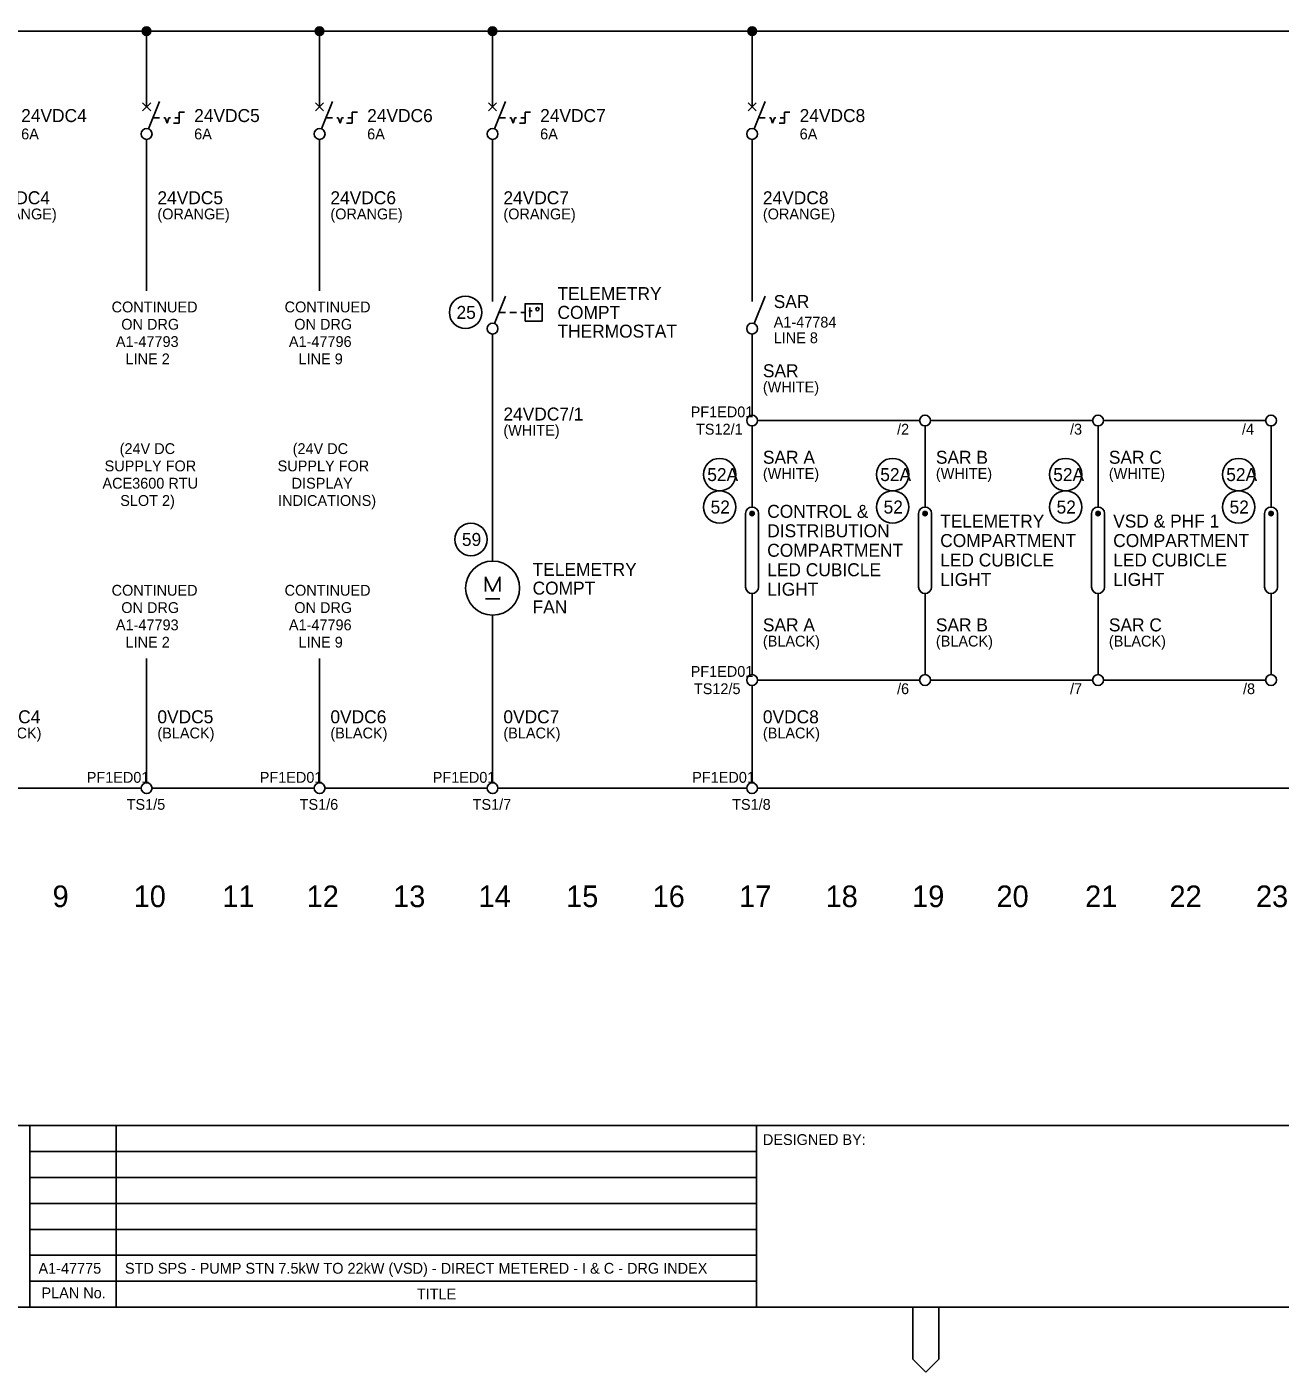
# Model space of a CAD drawing. Extents: x 0 to 841, y 0 to 594.
# Drawn here: x 212.3 to 502.1, y 0 to 311 of the extents above; entities that cross this region are included whole.
import ezdxf

# ---------------------------------------------------------------- set-up
doc = ezdxf.new("R2010")
doc.units = 0
for name, color, linetype in [('A1BORDER', 7, 'Continuous'), ('Level 1', 7, 'Continuous'), ('Level 10', 7, 'Continuous')]:
    doc.layers.add(name, color=color, linetype=linetype)

msp = doc.modelspace()

# ---------------------------------------------------------------- linework, layer by layer
at = {"layer": 'A1BORDER'}
for p, q in [((28, 57), (829, 57)), ((213, 15), (213, 57)), ((233, 15), (233, 57)), ((381, 15), (381, 57)), ((213, 51), (381, 51)), ((213, 45), (381, 45)), ((213, 39), (381, 39)), ((213, 33), (381, 33)), ((213, 27), (381, 27)), ((213, 21), (381, 21)), ((829, 15), (28, 15)), ((417.19, 15), (417.19, 3)), ((423.19, 15), (423.19, 3)), ((417.19, 3), (420.19, 0)), ((423.19, 3), (420.19, 0))]:
    msp.add_line(p, q, dxfattribs=at)
at = {"layer": 'Level 1'}
for p, q in [((80, 310), (580, 310)), ((240, 310), (240, 295)), ((280, 310), (280, 295)), ((320, 310), (320, 295)), ((380, 310), (380, 295)), ((239.06, 293.44), (240.94, 291.56)), ((240.94, 293.44), (239.06, 291.56)), ((240, 292.5), (240, 295)), ((240.46, 287.41), (243, 293.75)), ((279.06, 293.44), (280.94, 291.56)), ((280.94, 293.44), (279.06, 291.56)), ((280, 292.5), (280, 295)), ((280.46, 287.41), (283, 293.75)), ((319.06, 293.44), (320.94, 291.56)), ((320.94, 293.44), (319.06, 291.56)), ((320, 292.5), (320, 295)), ((320.46, 287.41), (323, 293.75)), ((379.06, 293.44), (380.94, 291.56)), ((380.94, 293.44), (379.06, 291.56)), ((380, 292.5), (380, 295)), ((380.46, 287.41), (383, 293.75)), ((240, 285), (240, 250)), ((280, 285), (280, 250)), ((320, 285), (320, 250)), ((380, 285), (380, 250)), ((320, 247.5), (320, 250)), ((380, 247.5), (380, 250)), ((380, 250), (380, 250)), ((320.46, 242.41), (323, 248.75)), ((321.5, 245), (323, 245)), ((324, 245), (325.5, 245)), ((326.5, 245), (327.5, 245)), ((320, 240), (320, 187.5)), ((380, 240), (380, 240)), ((380, 221.25), (380, 240)), ((380, 200), (380, 218.75)), ((381.25, 220), (418.75, 220)), ((420, 200), (420, 218.75)), ((421.25, 220), (458.75, 220)), ((460, 200), (460, 218.75)), ((461.25, 220), (498.75, 220)), ((500, 200), (500, 218.75)), ((380, 161.25), (380, 180)), ((420, 161.25), (420, 180)), ((460, 161.25), (460, 180)), ((500, 161.25), (500, 180)), ((320, 136.25), (320, 175)), ((240, 136.25), (240, 165)), ((280, 136.25), (280, 165)), ((380, 136.25), (380, 158.75)), ((381.25, 160), (418.75, 160)), ((421.25, 160), (458.75, 160)), ((461.25, 160), (498.75, 160)), ((201.25, 135), (238.75, 135)), ((241.25, 135), (278.75, 135)), ((281.25, 135), (318.75, 135)), ((321.25, 135), (378.75, 135)), ((381.25, 135), (538.75, 135))]:
    msp.add_line(p, q, dxfattribs=at)
msp.add_lwpolyline([(327.5, 243), (331.5, 243), (331.5, 247), (327.5, 247)], close=True, dxfattribs=at)
for points in [[(328.63, 246.13), (328.63, 243.87)], [(330.36, 245.38), (330.18, 245.42), (330.05, 245.56), (329.99, 245.76), (330.05, 245.94), (330.18, 246.07), (330.36, 246.13), (330.56, 246.07), (330.7, 245.94), (330.74, 245.76), (330.7, 245.56), (330.56, 245.42), (330.36, 245.38)], [(328.38, 245.38), (329.13, 245.38)]]:
    msp.add_lwpolyline(points, dxfattribs=at)
for centre, radius in [((240, 286.25), 1.25), ((280, 286.25), 1.25), ((320, 286.25), 1.25), ((380, 286.25), 1.25), ((313.75, 245), 3.75), ((320, 241.25), 1.25), ((380, 220), 1.25), ((420, 220), 1.25), ((460, 220), 1.25), ((500, 220), 1.25), ((372.5, 207.5), 3.75), ((412.5, 207.5), 3.75), ((452.5, 207.5), 3.75), ((492.5, 207.5), 3.75), ((372.5, 200), 3.75), ((412.5, 200), 3.75), ((452.5, 200), 3.75), ((492.5, 200), 3.75), ((315, 192.5), 3.75), ((380, 160), 1.25), ((420, 160), 1.25), ((460, 160), 1.25), ((500, 160), 1.25)]:
    msp.add_circle(centre, radius, dxfattribs=at)
at = {"layer": 'Level 10'}
for p, q in [((239, 310), (240.99, 310)), ((239.05, 310.3), (240.95, 310.3)), ((239.05, 309.7), (240.95, 309.7)), ((239.2, 310.6), (240.8, 310.6)), ((239.2, 309.4), (240.8, 309.4)), ((239.56, 310.9), (240.44, 310.9)), ((239.56, 309.1), (240.44, 309.1)), ((240, 311), (240, 311)), ((279, 310), (280.99, 310)), ((279.05, 310.3), (280.95, 310.3)), ((279.05, 309.7), (280.95, 309.7)), ((279.2, 310.6), (280.8, 310.6)), ((279.2, 309.4), (280.8, 309.4)), ((279.56, 310.9), (280.44, 310.9)), ((279.56, 309.1), (280.44, 309.1)), ((280, 311), (280, 311)), ((319, 310), (320.99, 310)), ((319.05, 310.3), (320.95, 310.3)), ((319.05, 309.7), (320.95, 309.7)), ((319.2, 310.6), (320.8, 310.6)), ((319.2, 309.4), (320.8, 309.4)), ((319.56, 310.9), (320.44, 310.9)), ((319.56, 309.1), (320.44, 309.1)), ((320, 311), (320, 311)), ((379, 310), (380.99, 310)), ((379.05, 310.3), (380.95, 310.3)), ((379.05, 309.7), (380.95, 309.7)), ((379.2, 310.6), (380.8, 310.6)), ((379.2, 309.4), (380.8, 309.4)), ((379.56, 310.9), (380.44, 310.9)), ((379.56, 309.1), (380.44, 309.1)), ((380, 311), (380, 311)), ((241.5, 290), (243, 290)), ((244, 290), (244.33, 290)), ((244.75, 288.75), (244.33, 290)), ((244.75, 288.75), (245.17, 290)), ((245.5, 290), (245.17, 290)), ((246.5, 290), (247.5, 290)), ((247.5, 288.75), (247.5, 291.25)), ((247.5, 291.25), (248.75, 291.25)), ((281.5, 290), (283, 290)), ((284, 290), (284.33, 290)), ((284.75, 288.75), (284.33, 290)), ((284.75, 288.75), (285.17, 290)), ((285.5, 290), (285.17, 290)), ((286.5, 290), (287.5, 290)), ((287.5, 288.75), (287.5, 291.25)), ((287.5, 291.25), (288.75, 291.25)), ((321.5, 290), (323, 290)), ((324, 290), (324.33, 290)), ((324.75, 288.75), (324.33, 290)), ((324.75, 288.75), (325.17, 290)), ((325.5, 290), (325.17, 290)), ((326.5, 290), (327.5, 290)), ((327.5, 288.75), (327.5, 291.25)), ((327.5, 291.25), (328.75, 291.25)), ((381.5, 290), (383, 290)), ((384, 290), (384.33, 290)), ((384.75, 288.75), (384.33, 290)), ((384.75, 288.75), (385.17, 290)), ((385.5, 290), (385.17, 290)), ((386.5, 290), (387.5, 290)), ((387.5, 288.75), (387.5, 291.25)), ((387.5, 291.25), (388.75, 291.25)), ((246.25, 288.75), (247.5, 288.75)), ((286.25, 288.75), (287.5, 288.75)), ((326.25, 288.75), (327.5, 288.75)), ((386.25, 288.75), (387.5, 288.75)), ((380.46, 242.41), (383, 248.75)), ((378.5, 181.5), (378.5, 198.5)), ((379.5, 198.5), (379.5, 198.5)), ((379.8, 198.04), (379.8, 198.96)), ((380.1, 198.01), (380.1, 198.99)), ((380.4, 198.2), (380.4, 198.8)), ((381.5, 198.5), (381.5, 181.5)), ((418.5, 181.5), (418.5, 198.5)), ((419.5, 198.5), (419.5, 198.5)), ((419.8, 198.04), (419.8, 198.96)), ((420.1, 198.01), (420.1, 198.99)), ((420.4, 198.2), (420.4, 198.8)), ((421.5, 198.5), (421.5, 181.5)), ((458.5, 181.5), (458.5, 198.5)), ((459.5, 198.5), (459.5, 198.5)), ((459.8, 198.04), (459.8, 198.96)), ((460.1, 198.01), (460.1, 198.99)), ((460.4, 198.2), (460.4, 198.8)), ((461.5, 198.5), (461.5, 181.5)), ((498.5, 181.5), (498.5, 198.5)), ((499.5, 198.5), (499.5, 198.5)), ((499.8, 198.04), (499.8, 198.96)), ((500.1, 198.01), (500.1, 198.99)), ((500.4, 198.2), (500.4, 198.8)), ((501.5, 198.5), (501.5, 181.5)), ((318.33, 180.5), (318.33, 183.83)), ((318.33, 183.83), (320, 180.5)), ((320, 180.5), (321.67, 183.83)), ((321.67, 183.83), (321.67, 180.5)), ((318.34, 178.75), (321.68, 178.75))]:
    msp.add_line(p, q, dxfattribs=at)
for centre, radius in [((240, 310), 1), ((280, 310), 1), ((320, 310), 1), ((380, 310), 1), ((380, 241.25), 1.25), ((380, 198.5), 0.5), ((420, 198.5), 0.5), ((460, 198.5), 0.5), ((500, 198.5), 0.5), ((320, 181.25), 6.25), ((240, 135), 1.25), ((280, 135), 1.25), ((320, 135), 1.25), ((380, 135), 1.25)]:
    msp.add_circle(centre, radius, dxfattribs=at)
for centre, start, end in [((380, 198.5), 0, 180), ((420, 198.5), 0, 180), ((460, 198.5), 0, 180), ((500, 198.5), 0, 180), ((380, 181.5), 180, 0), ((420, 181.5), 180, 0), ((460, 181.5), 180, 0), ((500, 181.5), 180, 0)]:
    msp.add_arc(centre, 1.5, start, end, dxfattribs=at)

# ---------------------------------------------------------------- texts
at = {"layer": 'A1BORDER'}
for s, p in [('DESIGNED BY:', (382.5, 52.5)), ('PLAN No.', (215.69, 17.06)), ('TITLE', (302.5, 16.81))]:
    msp.add_text(s, height=2.5, dxfattribs=at).set_placement(p)
at = {"layer": 'Level 1'}
for s, height, p in [('24VDC4', 3, (211, 289)), ('24VDC5', 3, (251, 289)), ('24VDC6', 3, (291, 289)), ('24VDC7', 3, (331, 289)), ('24VDC8', 3, (391, 289)), ('6A', 2.5, (211, 285)), ('6A', 2.5, (251, 285)), ('6A', 2.5, (291, 285)), ('6A', 2.5, (331, 285)), ('6A', 2.5, (391, 285)), ('24VDC4', 3, (202.5, 270)), ('24VDC5', 3, (242.5, 270)), ('24VDC6', 3, (282.5, 270)), ('24VDC7', 3, (322.5, 270)), ('24VDC8', 3, (382.5, 270)), ('(ORANGE)', 2.5, (202.5, 266.5)), ('(ORANGE)', 2.5, (242.5, 266.5)), ('(ORANGE)', 2.5, (282.5, 266.5)), ('(ORANGE)', 2.5, (322.5, 266.5)), ('(ORANGE)', 2.5, (382.5, 266.5)), ('TELEMETRY', 3, (335, 247.84)), ('SAR', 3, (385, 246)), ('CONTINUED', 2.5, (231.91, 245)), ('CONTINUED', 2.5, (271.91, 245)), ('25', 3, (311.66, 243.5)), ('COMPT', 3, (335, 243.5)), ('ON DRG', 2.5, (234.15, 241)), ('ON DRG', 2.5, (274.15, 241)), ('A1-47784', 2.5, (385, 241.5)), ('A1-47793', 2.5, (232.9, 237)), ('A1-47796', 2.5, (272.9, 237)), ('THERMOSTAT', 3, (335, 239.16)), ('LINE 8', 2.5, (385, 237.88)), ('LINE 2', 2.5, (235.14, 233)), ('LINE 9', 2.5, (275.14, 233)), ('SAR', 3, (382.5, 230)), ('(WHITE)', 2.5, (382.5, 226.5)), ('24VDC7/1', 3, (322.5, 220)), ('PF1ED01', 2.5, (365.8, 220.74)), ('(WHITE)', 2.5, (322.5, 216.5)), ('TS12/1', 2.5, (367.04, 216.74)), ('/2', 2.5, (413.52, 216.74)), ('/3', 2.5, (453.52, 216.74)), ('/4', 2.5, (493.27, 216.74)), ('(24V DC', 2.5, (233.77, 212.25)), ('(24V DC', 2.5, (273.77, 212.25)), ('SAR A', 3, (382.5, 210)), ('SAR B', 3, (422.5, 210)), ('SAR C', 3, (462.5, 210)), ('SUPPLY FOR', 2.5, (230.29, 208.25)), ('SUPPLY FOR', 2.5, (270.29, 208.25)), ('52A', 3, (369.64, 206)), ('(WHITE)', 2.5, (382.5, 206.5)), ('52A', 3, (409.64, 206)), ('(WHITE)', 2.5, (422.5, 206.5)), ('52A', 3, (449.64, 206)), ('(WHITE)', 2.5, (462.5, 206.5)), ('52A', 3, (489.64, 206)), ('ACE3600 RTU', 2.5, (229.79, 204.25)), ('DISPLAY', 2.5, (273.53, 204.25)), ('SLOT 2)', 2.5, (233.9, 200.25)), ('INDICATIONS)', 2.5, (270.41, 200.25)), ('52', 3, (370.41, 198.5)), ('CONTROL &', 3, (383.5, 197.5)), ('52', 3, (410.41, 198.5)), ('52', 3, (450.41, 198.5)), ('52', 3, (490.41, 198.5)), ('DISTRIBUTION', 3, (383.5, 193)), ('TELEMETRY', 3, (423.5, 195.25)), ('VSD & PHF 1', 3, (463.5, 195.25)), ('59', 3, (312.91, 191)), ('COMPARTMENT', 3, (423.5, 190.75)), ('COMPARTMENT', 3, (463.5, 190.75)), ('COMPARTMENT', 3, (383.5, 188.5)), ('TELEMETRY', 3, (329.25, 184.09)), ('LED CUBICLE', 3, (383.5, 184)), ('LED CUBICLE', 3, (423.5, 186.25)), ('LED CUBICLE', 3, (463.5, 186.25)), ('LIGHT', 3, (423.5, 181.75)), ('LIGHT', 3, (463.5, 181.75)), ('CONTINUED', 2.5, (231.91, 179.5)), ('CONTINUED', 2.5, (271.91, 179.5)), ('COMPT', 3, (329.25, 179.75)), ('LIGHT', 3, (383.5, 179.5)), ('ON DRG', 2.5, (234.15, 175.5)), ('ON DRG', 2.5, (274.15, 175.5)), ('FAN', 3, (329.25, 175.41)), ('SAR A', 3, (382.5, 171.25)), ('SAR B', 3, (422.5, 171.25)), ('SAR C', 3, (462.5, 171.25)), ('A1-47793', 2.5, (232.9, 171.5)), ('A1-47796', 2.5, (272.9, 171.5)), ('LINE 2', 2.5, (235.14, 167.5)), ('LINE 9', 2.5, (275.14, 167.5)), ('(BLACK)', 2.5, (382.5, 167.75)), ('(BLACK)', 2.5, (422.5, 167.75)), ('(BLACK)', 2.5, (462.5, 167.75)), ('PF1ED01', 2.5, (365.8, 160.74)), ('TS12/5', 2.5, (366.55, 156.74)), ('/6', 2.5, (413.52, 156.74)), ('/7', 2.5, (453.52, 156.74)), ('/8', 2.5, (493.52, 156.74)), ('0VDC4', 3, (202.5, 150)), ('0VDC5', 3, (242.5, 150)), ('0VDC6', 3, (282.5, 150)), ('0VDC7', 3, (322.5, 150)), ('0VDC8', 3, (382.5, 150)), ('(BLACK)', 2.5, (202.5, 146.5)), ('(BLACK)', 2.5, (242.5, 146.5)), ('(BLACK)', 2.5, (282.5, 146.5)), ('(BLACK)', 2.5, (322.5, 146.5)), ('(BLACK)', 2.5, (382.5, 146.5)), ('PF1ED01', 2.5, (226.16, 136.25)), ('PF1ED01', 2.5, (266.16, 136.25)), ('PF1ED01', 2.5, (306.16, 136.25)), ('PF1ED01', 2.5, (366.16, 136.25)), ('TS1/5', 2.5, (235.39, 130)), ('TS1/6', 2.5, (275.39, 130)), ('TS1/7', 2.5, (315.39, 130)), ('TS1/8', 2.5, (375.39, 130)), ('9', 5, (218.26, 107.5)), ('10', 5, (237.01, 107.5)), ('11', 5, (257.51, 107.5)), ('12', 5, (277.01, 107.5)), ('13', 5, (297.01, 107.5)), ('14', 5, (316.76, 107.5)), ('15', 5, (337.01, 107.5)), ('16', 5, (357.01, 107.5)), ('17', 5, (377.01, 107.5)), ('18', 5, (397.01, 107.5)), ('19', 5, (417.01, 107.5)), ('20', 5, (436.52, 107.5)), ('21', 5, (457.01, 107.5)), ('22', 5, (476.52, 107.5)), ('23', 5, (496.52, 107.5)), ('A1-47775', 2.5, (215, 22.75)), ('STD SPS - PUMP STN 7.5kW TO 22kW (VSD) - DIRECT METERED - I & C - DRG INDEX', 2.5, (235, 22.75))]:
    msp.add_text(s, height=height, dxfattribs=at).set_placement(p)

doc.saveas('drawing.dxf')
